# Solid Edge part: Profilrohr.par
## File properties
Username: bmolnar
Dokumentum tartalom típus: 0
Author: bmolnar
Last saved by: bmolnar
Revision: 82
Sűrűség: 0,000 kg/m^3
Pontosság: 0,990
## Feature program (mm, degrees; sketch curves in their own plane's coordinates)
base feature "unnamed BaseFeature 1"
thread "unnamed Thread 1"
thread "Menet_2"  ThreadDepth = 7.5 mm
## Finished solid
Body 1: solid body, 157 faces, 384 edges, 250 vertices.
  Faces by surface: plane 102, cylinder 41, cone 10, torus 4
  Edges by curve: line 284, circle 92, curve on surface 7, intersection 1
Bounding box of the edges (mm; curved faces can reach further): 80.000 x 86.000 x 72.000, from (-40, -40, 0) to (40, 46, 72).
Cylindrical faces by radius (mm): R1.6 x2, R4.283 x4, R4.55 x7, R4.555 x1, R7 x16, R31.5 x1, R32.35 x2, R32.55 x2, R34.1 x2, R53 x4
Conical faces (half-angle, radius in mm at the cone's reference point): 30 deg R31.825 x2, 30 deg R32.6387 x2, 45 deg R4.533 x2, 45 deg R32.7 x2, 45 deg R32.8 x2
Toroidal faces (ring radius, tube radius in mm): R33.9 r0.2 x4
Planar faces by outward normal: +x 9, +y 11, +z 8, -x 9, -y 9, -z 8, oblique 48
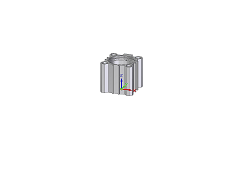
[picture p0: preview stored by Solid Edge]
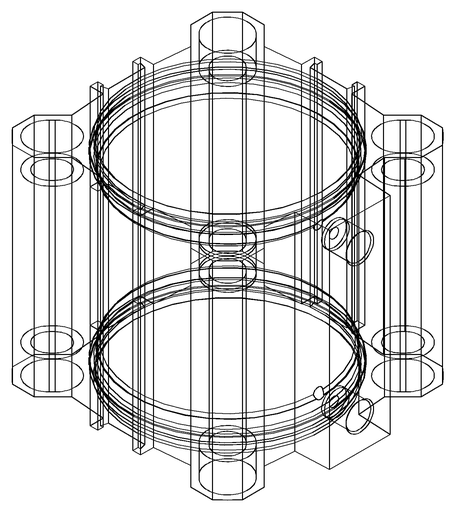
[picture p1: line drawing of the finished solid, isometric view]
